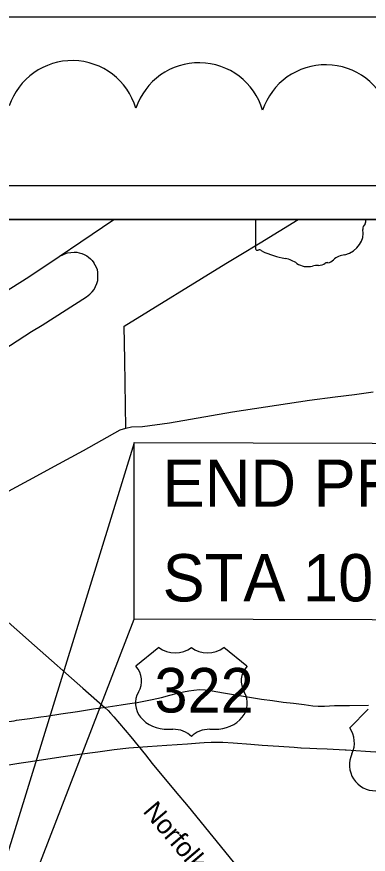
# Model space of a CAD drawing. Extents: x 0 to 96.2, y -27.5 to 31.3.
# Drawn here: x 47.878 to 48.919, y 18.907 to 21.387 of the extents above; entities that cross this region are included whole.
import ezdxf

# ---------------------------------------------------------------- set-up
doc = ezdxf.new("R2010")
doc.units = 0
for name, color, linetype in [('BOTTOM-BLKS', 7, 'Continuous'), ('DIM', 7, 'Continuous'), ('TB1', 7, 'Continuous'), ('TB_DUAL_PROF', 7, 'Continuous'), ('TB_PP_50x10_GRID', 7, 'Continuous'), ('TB_PROF_20x5', 7, 'Continuous'), ('TB_PSDSOD', 7, 'Continuous'), ('TB_SIGN_XS', 7, 'Continuous'), ('TB_SUPER_50x0-5', 7, 'Continuous'), ('TB_SUPER_50x1', 7, 'Continuous'), ('TB_SUPER_50x1_GRID', 7, 'Continuous')]:
    doc.layers.add(name, color=color, linetype=linetype)

msp = doc.modelspace()

# ---------------------------------------------------------------- linework, layer by layer
at = {"layer": 'BOTTOM-BLKS'}
msp.add_lwpolyline([(43.8234, 18.3711), (43.8234, 13.9869), (50.6234, 13.9869), (50.6234, 20.7869), (47.5697, 20.7869)], dxfattribs=at)
at = {"layer": 'DIM'}
msp.add_lwpolyline([(43.2234, 21.3869), (74.7234, 21.3869), (74.7234, 0.3869), (43.2234, 0.3869)], close=True, dxfattribs=at)
at = {"layer": 'TB1'}
for p, q in [((43.7234, 20.8869), (50.7234, 20.8869)), ((43.8234, 20.7869), (50.6234, 20.7869))]:
    msp.add_line(p, q, dxfattribs=at)
at = {"layer": 'TB_DUAL_PROF'}
for p, q in [((48.9114, 20.7869), (48.5851, 20.7869)), ((48.5851, 20.7869), (48.5851, 20.6998)), ((48.5851, 20.6998), (48.5851, 20.6998))]:
    msp.add_line(p, q, dxfattribs=at)
for centre, major_axis, start_param, end_param in [((48.8778, 20.7827), (0.0341, 0), 5.934695, 6.439194), ((48.8169, 20.7465), (0.0874, 0), 5.101752, 6.440018), ((48.9279, 20.7598), (0.0248, 0), 2.387724, 3.262537), ((48.589, 20.6993), (0.00385, 0), 3.00124, 4.508301), ((48.5895, 20.7198), (0.0294, 0), 4.665946, 4.897461), ((48.5956, 20.6882), (0.0106, 0), 0.519207, 1.627899), ((48.7294, 20.868), (0.2524, 0), 4.195997, 4.488961), ((48.8538, 20.6436), (0.0479, 0), 1.647645, 2.488434), ((48.6541, 20.6099), (0.079, 0), 0.823519, 1.323587), ((48.7395, 20.6872), (0.0501, 0), 4.026481, 4.996735), ((48.7722, 20.6722), (0.0267, 0), 4.691044, 5.507374), ((48.7963, 20.6529), (0.00752, 0), 1.147584, 2.315152), ((48.7931, 20.6804), (0.0282, 0), 4.937069, 5.64225), ((48.7685, 20.618), (0.0412, 0), 1.495662, 1.94098)]:
    msp.add_ellipse(centre, major_axis=major_axis, ratio=0.8, start_param=start_param, end_param=end_param, dxfattribs=at)
at = {"layer": 'TB_PP_50x10_GRID'}
for points in [[(48.0675, 20.721), (48.1654, 20.7869)], [(48.0033, 20.6774), (48.0675, 20.721)], [(48.0033, 20.6774), (48.0177, 20.6842), (48.0278, 20.6876), (48.0378, 20.6894), (48.0473, 20.6901), (48.0552, 20.6898), (48.0629, 20.6883), (48.0704, 20.6863), (48.0775, 20.6833), (48.085, 20.6789), (48.0903, 20.6754), (48.0961, 20.6706), (48.1012, 20.6654), (48.1062, 20.6584)], [(45.9055, 19.2703), (46.0888, 19.3884), (46.2568, 19.4882), (46.6429, 19.7608), (46.9371, 19.9661), (47.0729, 20.0637), (47.1791, 20.1395), (47.2478, 20.1879), (47.3438, 20.2535), (47.478, 20.3432), (47.913, 20.6171), (48.0033, 20.6774)], [(47.7731, 20.3597), (47.9208, 20.455), (47.9529, 20.4735), (48.0838, 20.5581), (48.0937, 20.5656), (48.1008, 20.5722), (48.1066, 20.5796), (48.1113, 20.588), (48.1153, 20.5973), (48.1176, 20.6064), (48.1179, 20.6159), (48.1177, 20.6245), (48.1176, 20.6312), (48.1164, 20.6378), (48.1136, 20.645), (48.1104, 20.6517), (48.1062, 20.6584)], [(47.7374, 19.6949), (47.9303, 19.5253), (48.0737, 19.3993), (48.1395, 19.3413), (48.148, 19.3328), (48.1554, 19.3246), (48.1649, 19.3142), (48.2159, 19.2549), (48.2587, 19.2019), (48.2786, 19.1763), (48.3467, 19.0938), (48.3852, 19.0484), (48.5316, 18.8694)]]:
    msp.add_lwpolyline(points, dxfattribs=at)
at = {"layer": 'TB_PSDSOD'}
for points in [[(48.196, 20.4704), (48.4967, 20.6567), (48.5363, 20.6805), (48.5993, 20.7171), (48.7116, 20.7869)], [(48.1976, 20.3699), (48.196, 20.4704)], [(48.2009, 20.1689), (48.1976, 20.3699)]]:
    msp.add_lwpolyline(points, dxfattribs=at)
at = {"layer": 'TB_SIGN_XS'}
for points in [[(48.2009, 20.1689), (48.2172, 20.1726), (48.2503, 20.1741), (48.3298, 20.185), (48.5171, 20.2176), (48.6794, 20.2419), (48.7446, 20.2519), (48.8206, 20.2613), (48.8781, 20.2684), (48.9334, 20.2769)], [(47.1415, 19.602), (47.1597, 19.6124), (47.1851, 19.6261), (47.2289, 19.6496), (47.6709, 19.885), (47.9366, 20.0273), (47.9789, 20.0501), (48.0261, 20.0756), (48.0751, 20.1023), (48.1844, 20.1637), (48.2009, 20.1689)], [(48.226, 19.3555), (48.2348, 19.3567), (48.2586, 19.3611), (48.2787, 19.3652), (48.3063, 19.3716), (48.3308, 19.3784), (48.3535, 19.3844), (48.3713, 19.3884), (48.3879, 19.3916), (48.4019, 19.3933), (48.4194, 19.3951), (48.4361, 19.3941), (48.457, 19.3914), (48.49, 19.3857), (48.5197, 19.3804), (48.5493, 19.3754), (48.579, 19.3705), (48.6029, 19.3663), (48.6352, 19.3625), (48.6667, 19.3579), (48.6979, 19.3542), (48.7294, 19.3504), (48.7552, 19.3469), (48.7704, 19.346), (48.7893, 19.3462), (48.8189, 19.3477), (48.8479, 19.3478), (48.864, 19.3479), (48.9194, 19.3486)], [(47.9487, 19.3138), (47.9661, 19.3164), (48.0081, 19.3226), (48.0573, 19.3301), (48.1046, 19.3375), (48.1489, 19.3442), (48.1869, 19.3499), (48.2062, 19.3528)], [(48.2062, 19.3528), (48.226, 19.3555)], [(47.6341, 19.2549), (47.6377, 19.2552), (47.6495, 19.2561), (47.6625, 19.2579), (47.6777, 19.2604), (47.7953, 19.2861), (47.8453, 19.2989), (47.8703, 19.3028), (47.8771, 19.3039), (47.9161, 19.3089), (47.9416, 19.3128), (47.9487, 19.3138)], [(47.8852, 19.1769), (47.8907, 19.1779), (47.9109, 19.1813), (47.951, 19.1871), (48.0082, 19.1954), (48.0638, 19.2037), (48.1183, 19.2109), (48.166, 19.2175), (48.2092, 19.2223), (48.2649, 19.2264), (48.3221, 19.2302), (48.3831, 19.2343), (48.4191, 19.237), (48.4194, 19.237)], [(48.4194, 19.237), (48.4331, 19.238), (48.454, 19.239), (48.468, 19.2396), (48.4881, 19.2387), (48.5192, 19.2368), (48.5709, 19.2329), (48.6043, 19.2303), (48.654, 19.2271), (48.6999, 19.2243), (48.7197, 19.2229)], [(48.7197, 19.2229), (48.72, 19.2229), (48.7462, 19.2211), (48.7671, 19.2206), (48.7978, 19.2191), (48.8507, 19.2161), (48.8532, 19.216), (48.9113, 19.2129), (48.9568, 19.2097), (49.0039, 19.208), (49.0555, 19.2056), (49.0961, 19.2035), (49.1606, 19.2001)], [(47.2664, 19.0754), (47.2811, 19.0776), (47.4061, 19.0963), (47.4742, 19.1074), (47.5484, 19.1201), (47.6165, 19.1312), (47.6657, 19.139), (47.7179, 19.1484), (47.7796, 19.1587), (47.8424, 19.1698), (47.8841, 19.1768), (47.885, 19.1769), (47.8852, 19.1769)]]:
    msp.add_lwpolyline(points, dxfattribs=at)
at = {"layer": 'TB_SUPER_50x0-5'}
for p, q in [((48.2989, 19.5192), (48.2302, 19.4643)), ((48.5598, 19.4643), (48.4912, 19.5192)), ((48.9191, 19.3368), (48.8642, 19.2819)), ((48.3264, 19.2775), (48.3401, 19.2775)), ((48.45, 19.2775), (48.4637, 19.2775))]:
    msp.add_line(p, q, dxfattribs=at)
for centre, start, end in [((48.8012, 19.2378), 334.5471, 35.0009), ((48.9403, 19.172), 154.8319, 270.6383)]:
    msp.add_arc(centre, 0.0769, start, end, dxfattribs=at)
for centre, major_axis, start_param, end_param in [((48.347, 19.5585), (-0.0687, 0), 0.795399, 2.346194), ((48.4431, 19.5585), (-0.0687, 0), 0.795399, 2.346194), ((48.1515, 19.4202), (0.0961, 0), 5.838949, 6.894067), ((48.6386, 19.4202), (-0.0961, 0), 5.672304, 6.727422), ((48.3253, 19.3544), (0.0961, 0), 2.702327, 4.723529), ((48.4648, 19.3544), (-0.0961, 0), 1.559657, 3.580859), ((48.3401, 19.2226), (-0.0687, 0), 3.785094, 4.712389), ((48.45, 19.2226), (-0.0687, 0), 4.712389, 5.639684)]:
    msp.add_ellipse(centre, major_axis=major_axis, ratio=0.8, start_param=start_param, end_param=end_param, dxfattribs=at)
at = {"layer": 'TB_SUPER_50x1'}
for points in [[(48.2252, 20.1257), (47.4236, 17.5299), (48.2252, 19.6035)], [(48.2252, 20.1261), (49.9878, 20.1215), (49.9878, 19.5988), (48.2252, 19.6035)]]:
    msp.add_lwpolyline(points, close=True, dxfattribs=at)
at = {"layer": 'TB_SUPER_50x1_GRID'}
for centre, start, end in [((48.0418, 21.0603), 16.5143, 161.5143), ((48.4173, 21.054), 16.5686, 161.5686), ((48.7928, 21.0481), 16.6373, 161.6373)]:
    msp.add_arc(centre, 0.1968, start, end, dxfattribs=at)

# ---------------------------------------------------------------- texts
at = {"layer": 'TB_PROF_20x5'}
msp.add_text('Norfolk Southern Railway', height=0.056629, rotation=310.3696, dxfattribs=at).set_placement((48.2491, 19.0333))
at = {"layer": 'TB_SUPER_50x0-5'}
msp.add_text('322', height=0.13184, dxfattribs=at).set_placement((48.2855, 19.327))
at = {"layer": 'TB_SUPER_50x1'}
for s, p in [('END PROJECT', (48.3097, 19.936)), ('STA 1020+67.19', (48.3097, 19.656))]:
    msp.add_text(s, height=0.14, dxfattribs=at).set_placement(p)

doc.saveas('drawing.dxf')
